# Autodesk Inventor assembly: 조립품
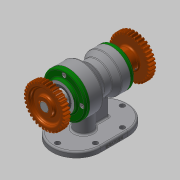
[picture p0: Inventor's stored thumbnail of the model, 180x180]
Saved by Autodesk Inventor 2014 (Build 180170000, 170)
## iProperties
Created: 2020-01
Part Number: 조립품
Document SubType Name: Assembly
Designer: kh
Author: kh
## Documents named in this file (13)
- C:\Users\kh\Desktop\700104V1021\조립품.iam
- C:\Users\kh\Desktop\700104V1021\본체.ipt
- C:\Users\kh\Desktop\700104V1021\뒤커버.ipt
- C:\Users\kh\Desktop\700104V1021\앞커버.ipt
- C:\Users\kh\Desktop\700104V1021\베어링 6203.ipt
- C:\Users\kh\Desktop\700104V1021\베어링 6205.ipt
- C:\Users\kh\Desktop\700104V1021\오일 실 17 30 8.ipt
- C:\Users\kh\Desktop\700104V1021\오일 실 25 38 8.ipt
- C:\Users\kh\Desktop\700104V1021\축.ipt
- C:\Users\kh\Desktop\700104V1021\Ű 5 x 5 x 18.ipt
- C:\Users\kh\Desktop\700104V1021\스퍼기어.ipt
- C:\Users\kh\Desktop\700104V1021\멈춤나사 M3.ipt
- C:\Users\kh\Desktop\700104V1021\볼트 M4.ipt
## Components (2 placed, 1 different names)
1. Ű 5 x 5 x 18:1
2. Ű 5 x 5 x 18:2
